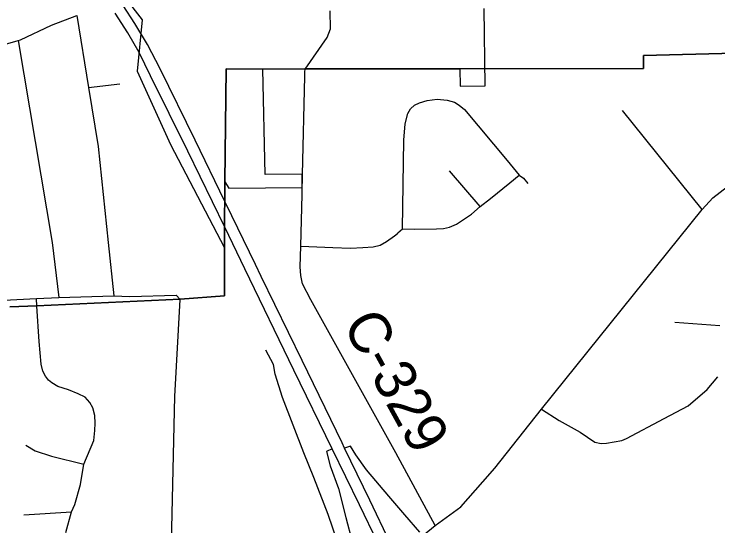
# Model space of a CAD drawing. Extents: x -59 to 82, y -3 to 49.
# Drawn here: x -54.449 to -53.486, y 44.096 to 44.796 of the extents above; entities that cross this region are included whole.
import ezdxf

# ---------------------------------------------------------------- set-up
doc = ezdxf.new("R2010")
doc.units = 0
for name, color, linetype in [('GM_X_Corporation', 7, 'Continuous'), ('GM_X_County_Road', 7, 'Continuous'), ('GM_X_County_Road_Text', 7, 'Continuous'), ('GM_X_Interchange_Ramps', 7, 'Continuous'), ('GM_X_State_Route', 7, 'Continuous'), ('GM_X_Township_Road', 7, 'Continuous')]:
    doc.layers.add(name, color=color, linetype=linetype)

msp = doc.modelspace()

# ---------------------------------------------------------------- linework, layer by layer
at = {"layer": 'GM_X_Corporation'}
for p, q in [((-54.31123, 44.83707), (-54.27329, 44.78832)), ((-53.80419, 44.69776), (-53.80573, 44.80399)), ((-54.27329, 44.78832), (-54.28001, 44.71795)), ((-53.58772, 44.73941), (-53.2204, 44.74916)), ((-53.2204, 44.74916), (-53.58772, 44.73941)), ((-53.58772, 44.72169), (-53.58772, 44.73941)), ((-53.58772, 44.73941), (-53.58772, 44.72169)), ((-54.28001, 44.71795), (-54.23449, 44.61755)), ((-54.16013, 44.56659), (-54.15845, 44.72114)), ((-54.15845, 44.72114), (-54.16013, 44.56659)), ((-54.15845, 44.72114), (-54.10822, 44.72084)), ((-54.10822, 44.72084), (-54.15845, 44.72114)), ((-54.10822, 44.72084), (-54.05078, 44.72114)), ((-54.10822, 44.72084), (-54.05078, 44.72114)), ((-54.05078, 44.72114), (-54.10822, 44.72084)), ((-54.1051, 44.57655), (-54.10822, 44.72084)), ((-54.05078, 44.72114), (-53.83905, 44.72114)), ((-54.05078, 44.72114), (-53.83905, 44.72114)), ((-53.83905, 44.72114), (-54.05078, 44.72114)), ((-53.83905, 44.72114), (-53.58772, 44.72169)), ((-53.58772, 44.72169), (-53.83905, 44.72114)), ((-53.83905, 44.72114), (-53.83847, 44.69743)), ((-53.83847, 44.69743), (-53.80419, 44.69776)), ((-54.23449, 44.61755), (-54.16065, 44.47646)), ((-54.05433, 44.57689), (-54.1051, 44.57655)), ((-54.05467, 44.55896), (-54.05433, 44.57689)), ((-54.16065, 44.47646), (-54.16013, 44.56659)), ((-54.16041, 44.54014), (-54.16013, 44.56659)), ((-54.16013, 44.56659), (-54.16041, 44.54014)), ((-54.16013, 44.56659), (-54.15498, 44.55783)), ((-54.15498, 44.55783), (-54.05467, 44.55896)), ((-54.1606, 44.52257), (-54.16041, 44.54014)), ((-54.16041, 44.54014), (-54.1606, 44.52257)), ((-54.16062, 44.50487), (-54.1606, 44.52257)), ((-54.1606, 44.52257), (-54.16062, 44.50487)), ((-54.16065, 44.47646), (-54.16062, 44.50487)), ((-54.16062, 44.50487), (-54.16065, 44.47646)), ((-54.16073, 44.41068), (-54.16065, 44.47646)), ((-54.16065, 44.47646), (-54.16073, 44.41068)), ((-54.41754, 44.39676), (-54.22159, 44.40621)), ((-54.22159, 44.40621), (-54.41754, 44.39676)), ((-54.22159, 44.40621), (-54.16073, 44.41068)), ((-54.16073, 44.41068), (-54.22159, 44.40621)), ((-54.45437, 44.39565), (-54.41754, 44.39676)), ((-54.41754, 44.39676), (-54.45437, 44.39565))]:
    msp.add_line(p, q, dxfattribs=at)
at = {"layer": 'GM_X_County_Road'}
for p, q in [((-54.01586, 44.77611), (-54.01622, 44.80073)), ((-54.02027, 44.76399), (-54.01586, 44.77611)), ((-54.05058, 44.72058), (-54.02027, 44.76399)), ((-54.05091, 44.71124), (-54.05077, 44.71732)), ((-54.05077, 44.71732), (-54.05058, 44.72058)), ((-54.05412, 44.57633), (-54.05091, 44.71124)), ((-54.05426, 44.56936), (-54.05412, 44.57633)), ((-54.05447, 44.5584), (-54.05426, 44.56936)), ((-54.05469, 44.54931), (-54.05447, 44.5584)), ((-54.05639, 44.47867), (-54.05469, 44.54931)), ((-54.05749, 44.45044), (-54.05639, 44.47867)), ((-54.05639, 44.43826), (-54.05749, 44.45044)), ((-54.05418, 44.42719), (-54.05639, 44.43826)), ((-54.04255, 44.40505), (-54.05418, 44.42719)), ((-53.92641, 44.19562), (-54.04255, 44.40505)), ((-53.87281, 44.0963), (-53.92641, 44.19562))]:
    msp.add_line(p, q, dxfattribs=at)
at = {"layer": 'GM_X_Interchange_Ramps'}
for p, q in [((-53.98858, 44.20466), (-53.99644, 44.20201)), ((-53.98112, 44.19296), (-53.98858, 44.20466)), ((-54.01364, 44.20118), (-54.02124, 44.19746)), ((-54.02124, 44.19746), (-54.01616, 44.17775)), ((-53.96657, 44.17246), (-53.98112, 44.19296)), ((-54.01616, 44.17775), (-54.00492, 44.14666)), ((-53.9358, 44.13647), (-53.96657, 44.17246)), ((-54.00492, 44.14666), (-53.99478, 44.10716)), ((-53.91397, 44.11086), (-53.9358, 44.13647)), ((-53.89383, 44.08698), (-53.91397, 44.11086)), ((-53.99478, 44.10716), (-53.98632, 44.07423))]:
    msp.add_line(p, q, dxfattribs=at)
at = {"layer": 'GM_X_State_Route'}
for p, q in [((-54.28329, 44.78351), (-54.29951, 44.80808)), ((-54.29294, 44.77058), (-54.31027, 44.79756)), ((-54.26602, 44.75448), (-54.28329, 44.78351)), ((-54.27759, 44.74339), (-54.29294, 44.77058)), ((-54.2486, 44.72123), (-54.26602, 44.75448)), ((-54.26202, 44.71158), (-54.27759, 44.74339)), ((-54.20107, 44.62356), (-54.2486, 44.72123)), ((-54.21114, 44.60872), (-54.26202, 44.71158)), ((-54.16021, 44.53958), (-54.20107, 44.62356)), ((-54.16042, 44.50431), (-54.21114, 44.60872)), ((-53.49287, 44.54477), (-53.40937, 44.6094)), ((-53.50741, 44.5285), (-53.49287, 44.54477)), ((-54.15889, 44.53686), (-54.16021, 44.53958)), ((-54.11854, 44.45341), (-54.15889, 44.53686)), ((-53.72734, 44.25565), (-53.50741, 44.5285)), ((-54.13305, 44.44773), (-54.16042, 44.50431)), ((-54.06594, 44.30868), (-54.13305, 44.44773)), ((-54.11059, 44.43712), (-54.11854, 44.45341)), ((-54.05446, 44.32224), (-54.11059, 44.43712)), ((-53.99963, 44.20929), (-54.05446, 44.32224)), ((-54.01364, 44.20118), (-54.06594, 44.30868)), ((-53.79109, 44.17455), (-53.72734, 44.25565)), ((-53.99644, 44.20201), (-53.99963, 44.20929)), ((-53.97605, 44.12435), (-54.01364, 44.20118)), ((-53.96182, 44.13108), (-53.99644, 44.20201)), ((-53.80739, 44.15603), (-53.79109, 44.17455)), ((-53.83738, 44.12196), (-53.80739, 44.15603)), ((-53.92919, 44.0626), (-53.96182, 44.13108)), ((-53.94018, 44.05016), (-53.97605, 44.12435)), ((-53.87281, 44.0963), (-53.83738, 44.12196)), ((-53.88988, 44.08224), (-53.87281, 44.0963))]:
    msp.add_line(p, q, dxfattribs=at)
at = {"layer": 'GM_X_Township_Road'}
for p, q in [((-54.39724, 44.78095), (-54.36277, 44.79443)), ((-54.36277, 44.79443), (-54.34669, 44.69571)), ((-54.43982, 44.76106), (-54.39724, 44.78095)), ((-54.48895, 44.74638), (-54.44274, 44.76019)), ((-54.44274, 44.76019), (-54.43982, 44.76106)), ((-54.44274, 44.76019), (-54.39668, 44.48374)), ((-54.34669, 44.69571), (-54.30389, 44.70092)), ((-54.34669, 44.69571), (-54.33356, 44.615)), ((-53.89419, 44.67492), (-53.8834, 44.67796)), ((-53.8834, 44.67796), (-53.86983, 44.67989)), ((-53.86983, 44.67989), (-53.85628, 44.67851)), ((-53.85628, 44.67851), (-53.84631, 44.67574)), ((-53.84631, 44.67574), (-53.83967, 44.67131)), ((-53.90997, 44.66024), (-53.90637, 44.66633)), ((-53.90637, 44.66633), (-53.90111, 44.67131)), ((-53.90111, 44.67131), (-53.89419, 44.67492)), ((-53.83967, 44.67131), (-53.83275, 44.6655)), ((-53.91357, 44.64585), (-53.90997, 44.66024)), ((-53.83275, 44.6655), (-53.77407, 44.59575)), ((-53.50741, 44.5285), (-53.61624, 44.66414)), ((-53.91551, 44.62343), (-53.91357, 44.64585)), ((-53.91716, 44.50248), (-53.91551, 44.62343)), ((-54.33356, 44.615), (-54.31997, 44.48348)), ((-53.77407, 44.59575), (-53.75774, 44.57555)), ((-53.81116, 44.53292), (-53.85295, 44.58164)), ((-53.77075, 44.56531), (-53.75774, 44.57555)), ((-53.75774, 44.57555), (-53.75193, 44.57167)), ((-53.75193, 44.57167), (-53.74584, 44.5642)), ((-53.79704, 44.54399), (-53.77075, 44.56531)), ((-53.81116, 44.53292), (-53.79704, 44.54399)), ((-53.82278, 44.52241), (-53.81116, 44.53292)), ((-53.84354, 44.50857), (-53.82278, 44.52241)), ((-53.92353, 44.49666), (-53.91716, 44.50248)), ((-53.91716, 44.50248), (-53.90139, 44.50165)), ((-53.87067, 44.5022), (-53.86126, 44.50275)), ((-53.86126, 44.50275), (-53.85295, 44.50441)), ((-53.85295, 44.50441), (-53.84354, 44.50857)), ((-53.92824, 44.49251), (-53.92432, 44.49597)), ((-53.92432, 44.49597), (-53.92353, 44.49666)), ((-53.90139, 44.50165), (-53.87067, 44.5022)), ((-54.39668, 44.48374), (-54.38748, 44.40819)), ((-54.31997, 44.48348), (-54.31226, 44.41053)), ((-53.94789, 44.47978), (-53.93903, 44.48504)), ((-53.93903, 44.48504), (-53.92824, 44.49251)), ((-54.05639, 44.47867), (-54.01238, 44.47674)), ((-54.01238, 44.47674), (-53.9883, 44.4759)), ((-53.9883, 44.4759), (-53.9717, 44.47674)), ((-53.9717, 44.47674), (-53.9573, 44.47757)), ((-53.9573, 44.47757), (-53.94789, 44.47978)), ((-54.46252, 44.40458), (-54.41803, 44.40676)), ((-54.41803, 44.40676), (-54.38748, 44.40819)), ((-54.41734, 44.3962), (-54.41803, 44.40676)), ((-54.38748, 44.40819), (-54.31226, 44.41053)), ((-54.31226, 44.41053), (-54.29046, 44.40976)), ((-54.29046, 44.40976), (-54.22695, 44.41142)), ((-54.22695, 44.41142), (-54.22139, 44.40565)), ((-54.22861, 44.27268), (-54.22139, 44.40565)), ((-54.41419, 44.34801), (-54.41734, 44.3962)), ((-53.48347, 44.36934), (-53.54469, 44.37416)), ((-54.41164, 44.31709), (-54.41419, 44.34801)), ((-54.09371, 44.31651), (-54.10446, 44.3363)), ((-54.40935, 44.30739), (-54.41164, 44.31709)), ((-54.09156, 44.30317), (-54.09371, 44.31651)), ((-54.40551, 44.30075), (-54.40935, 44.30739)), ((-54.40168, 44.29509), (-54.40551, 44.30075)), ((-54.08167, 44.27134), (-54.09156, 44.30317)), ((-54.39683, 44.29129), (-54.40168, 44.29509)), ((-54.38857, 44.28637), (-54.39683, 44.29129)), ((-53.50081, 44.28251), (-53.48598, 44.29978)), ((-54.37421, 44.28198), (-54.38857, 44.28637)), ((-54.36113, 44.27641), (-54.37421, 44.28198)), ((-53.52642, 44.25988), (-53.50081, 44.28251)), ((-54.35111, 44.27168), (-54.36113, 44.27641)), ((-54.34491, 44.26462), (-54.35111, 44.27168)), ((-54.2336, 44.06374), (-54.22861, 44.27268)), ((-54.05242, 44.19562), (-54.08167, 44.27134)), ((-54.34081, 44.25748), (-54.34491, 44.26462)), ((-54.33831, 44.2469), (-54.34081, 44.25748)), ((-53.72734, 44.25565), (-53.70314, 44.24012)), ((-53.55952, 44.24255), (-53.52642, 44.25988)), ((-54.33747, 44.23632), (-54.33831, 44.2469)), ((-53.61074, 44.21509), (-53.55952, 44.24255)), ((-54.33806, 44.22643), (-54.33747, 44.23632)), ((-53.70314, 44.24012), (-53.67443, 44.22386)), ((-54.33943, 44.21233), (-54.33806, 44.22643)), ((-53.67443, 44.22386), (-53.65445, 44.21011)), ((-53.61729, 44.21244), (-53.61074, 44.21509)), ((-54.43266, 44.20597), (-54.41957, 44.19818)), ((-54.35334, 44.18008), (-54.33943, 44.21233)), ((-53.65445, 44.21011), (-53.64571, 44.20839)), ((-53.64571, 44.20839), (-53.63852, 44.2087)), ((-53.63852, 44.2087), (-53.61729, 44.21244)), ((-54.41957, 44.19818), (-54.39759, 44.19122)), ((-54.03866, 44.16207), (-54.05242, 44.19562)), ((-54.39759, 44.19122), (-54.35334, 44.18008)), ((-54.35793, 44.1524), (-54.35334, 44.18008)), ((-54.01888, 44.1113), (-54.03866, 44.16207)), ((-54.36537, 44.12498), (-54.35793, 44.1524)), ((-54.37017, 44.11492), (-54.36537, 44.12498)), ((-54.43537, 44.11062), (-54.37017, 44.11492)), ((-54.37759, 44.0868), (-54.37017, 44.11492)), ((-53.9886, 44.02165), (-54.01888, 44.1113))]:
    msp.add_line(p, q, dxfattribs=at)

# ---------------------------------------------------------------- texts
at = {"layer": 'GM_X_County_Road_Text'}
msp.add_text('C-329', height=0.056818, rotation=298.8007, dxfattribs=at).set_placement((-54.00012, 44.3716))

doc.saveas('drawing.dxf')
